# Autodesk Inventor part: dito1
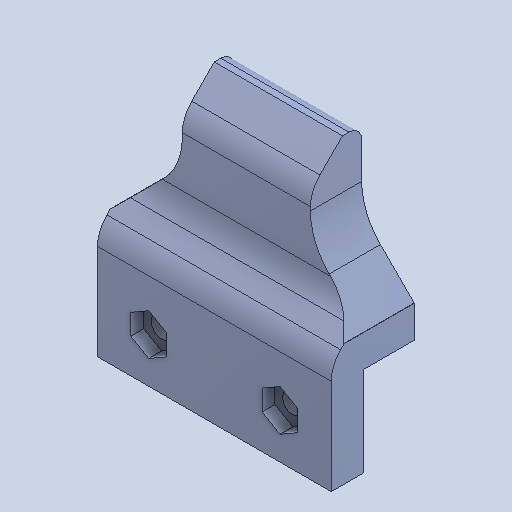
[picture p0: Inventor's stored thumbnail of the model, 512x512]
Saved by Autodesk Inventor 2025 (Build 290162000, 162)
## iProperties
Created: 2025-06
Part Number: dito1
Material: Gomma, Silicone
Document SubType Name: Modeling
Designer: Ryzen5700u
Density: 1.25 g/cm^3
Appearance: Default
Author: Ryzen5700u
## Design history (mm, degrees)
feature "Solido1"
node "Solido2"
